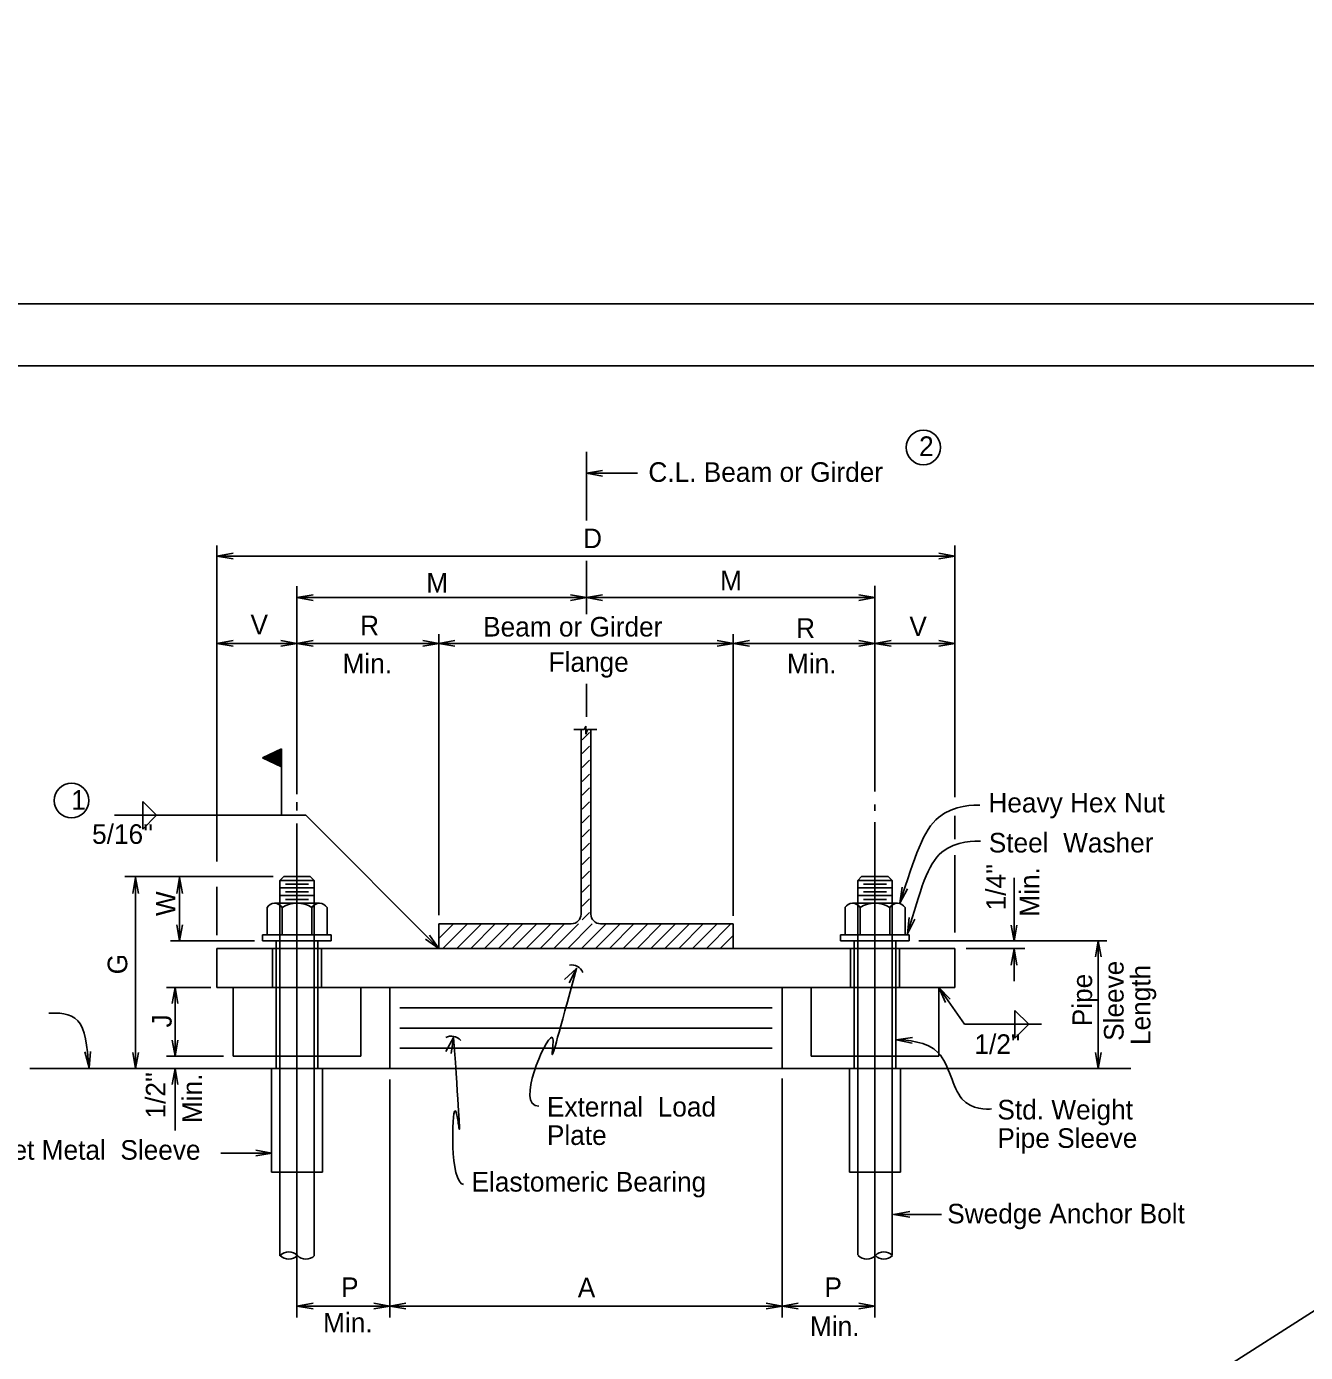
# Model space of a CAD drawing. Extents: x 113 to 232, y -103 to -27.
# Drawn here: x 159.73 to 165.17, y -32.24 to -26.61 of the extents above; entities that cross this region are included whole.
import ezdxf

# ---------------------------------------------------------------- set-up
doc = ezdxf.new("R2010")
doc.units = 0
for name, color, linetype in [('1', 7, 'Continuous'), ('B_Border', 7, 'Continuous'), ('B_Dimension', 7, 'Continuous'), ('B_No_Plot', 7, 'Continuous')]:
    doc.layers.add(name, color=color, linetype=linetype)

msp = doc.modelspace()

# ---------------------------------------------------------------- linework, layer by layer
at = {"layer": '1'}
for p, q in [((147.5029, -43.3409), (173.7742, -26.6088)), ((162.1117, -28.7088), (162.1117, -28.4165)), ((162.1117, -28.5077), (162.329, -28.5077)), ((160.5416, -30.1572), (160.5416, -28.8149)), ((163.6775, -29.8845), (163.6775, -28.8149)), ((160.5416, -28.8595), (163.6775, -28.8595)), ((162.1117, -29.1067), (162.1117, -28.8797)), ((160.8816, -29.8713), (160.8816, -28.9872)), ((163.3375, -29.8606), (163.3375, -28.9863)), ((160.8816, -29.0363), (162.1117, -29.0363)), ((162.1117, -29.0363), (163.3375, -29.0363)), ((161.4845, -30.3862), (161.4845, -29.1915)), ((162.7345, -30.3886), (162.7345, -29.1915)), ((160.5416, -29.231), (160.8816, -29.231)), ((160.8816, -29.231), (161.4845, -29.231)), ((161.4845, -29.231), (162.7359, -29.231)), ((162.7359, -29.231), (163.3375, -29.231)), ((163.3375, -29.231), (163.6775, -29.231)), ((162.1117, -29.5426), (162.1117, -29.4022)), ((162.1014, -29.597), (162.1093, -29.5829)), ((162.1093, -29.5829), (162.1093, -29.616)), ((162.0579, -29.597), (162.1014, -29.597)), ((162.0888, -29.597), (162.0888, -30.3813)), ((162.1093, -29.616), (162.1154, -29.597)), ((162.1154, -29.597), (162.1558, -29.597)), ((162.1303, -30.3813), (162.1303, -29.597)), ((160.816, -29.6793), (160.735, -29.7171)), ((160.816, -29.6793), (160.816, -29.6787)), ((160.816, -29.7548), (160.816, -29.6793)), ((160.735, -29.7171), (160.816, -29.7548)), ((160.816, -29.7548), (160.816, -29.7853)), ((160.816, -29.7853), (160.816, -29.9615)), ((160.2261, -30.0205), (160.2261, -29.9025)), ((160.2261, -29.9025), (160.2851, -29.9615)), ((160.8816, -29.9414), (160.8816, -29.9054)), ((163.3375, -29.9429), (163.3375, -29.9155)), ((160.9189, -29.9615), (160.1068, -29.9615)), ((160.2851, -29.9615), (160.2261, -30.0205)), ((161.4845, -30.5271), (160.9189, -29.9615)), ((163.6775, -30.0629), (163.6775, -29.9632)), ((160.8816, -32.0955), (160.8816, -29.9969)), ((163.3375, -32.0955), (163.3375, -29.99)), ((163.6775, -30.4598), (163.6775, -30.1312)), ((160.781, -30.2217), (160.1497, -30.2217)), ((160.1958, -31.0376), (160.1958, -30.2253)), ((160.3824, -30.495), (160.3824, -30.2253)), ((160.825, -30.2217), (160.8086, -30.238)), ((160.8086, -30.3352), (160.8086, -30.238)), ((160.8086, -30.238), (160.9545, -30.238)), ((160.825, -30.2217), (160.9381, -30.2217)), ((160.833, -30.2543), (160.9301, -30.2543)), ((160.9381, -30.2217), (160.9545, -30.238)), ((160.9545, -30.3352), (160.9545, -30.238)), ((163.2646, -30.238), (163.2809, -30.2217)), ((163.2646, -30.238), (163.4104, -30.238)), ((163.2646, -30.3352), (163.2646, -30.238)), ((163.2646, -30.238), (163.4104, -30.238)), ((163.2809, -30.2217), (163.3941, -30.2217)), ((163.2889, -30.2543), (163.3861, -30.2543)), ((163.3941, -30.2217), (163.4104, -30.238)), ((163.4104, -30.3352), (163.4104, -30.238)), ((163.9288, -30.4962), (163.9288, -30.2272)), ((160.5416, -30.4716), (160.5416, -30.2656)), ((160.8086, -30.2704), (160.9545, -30.2704)), ((160.8086, -30.3028), (160.9545, -30.3028)), ((160.833, -30.2868), (160.9301, -30.2868)), ((160.833, -30.3191), (160.9301, -30.3191)), ((163.2646, -30.2704), (163.4104, -30.2704)), ((163.2646, -30.3028), (163.4104, -30.3028)), ((163.2889, -30.2868), (163.3861, -30.2868)), ((163.2889, -30.3191), (163.3861, -30.3191)), ((160.7542, -30.469), (160.7542, -30.3535)), ((160.7863, -30.3352), (160.9771, -30.3352)), ((160.8086, -31.0376), (160.8086, -30.3352)), ((160.8186, -30.469), (160.8186, -30.3535)), ((160.9447, -30.469), (160.9447, -30.3535)), ((160.9545, -31.0376), (160.9545, -30.3352)), ((161.0093, -30.469), (161.0093, -30.3535)), ((163.2102, -30.469), (163.2102, -30.3535)), ((163.2422, -30.3352), (163.433, -30.3352)), ((163.2646, -31.0376), (163.2646, -30.3352)), ((163.2745, -30.469), (163.2745, -30.3535)), ((163.4007, -30.469), (163.4007, -30.3535)), ((163.4104, -31.0376), (163.4104, -30.3352)), ((163.4652, -30.469), (163.4652, -30.3535)), ((162.0471, -30.4229), (161.4845, -30.4229)), ((161.4845, -30.4229), (161.4845, -30.5271)), ((162.7345, -30.4229), (162.1719, -30.4229)), ((162.7345, -30.5271), (162.7345, -30.4229)), ((160.7357, -30.469), (161.0274, -30.469)), ((160.7357, -30.469), (160.7357, -30.495)), ((161.0274, -30.469), (161.0274, -30.495)), ((163.1917, -30.469), (163.4833, -30.469)), ((163.1917, -30.469), (163.1917, -30.495)), ((163.4833, -30.469), (163.4833, -30.495)), ((160.7005, -30.495), (160.3437, -30.495)), ((160.5416, -30.6938), (160.5416, -30.5271)), ((160.5416, -30.5271), (163.6775, -30.5271)), ((160.7357, -30.495), (161.0274, -30.495)), ((160.7775, -30.6938), (160.7775, -30.5283)), ((160.7931, -30.5283), (160.7931, -30.4953)), ((160.7931, -30.6938), (160.7931, -30.5283)), ((160.9701, -30.5283), (160.9701, -30.4953)), ((160.9701, -30.6936), (160.9701, -30.5283)), ((160.9856, -30.6938), (160.9856, -30.5283)), ((163.1917, -30.495), (163.4833, -30.495)), ((163.2334, -30.6947), (163.2334, -30.5279)), ((163.249, -30.5279), (163.249, -30.4946)), ((163.249, -30.6947), (163.249, -30.5279)), ((163.426, -30.5279), (163.426, -30.4956)), ((163.426, -30.6957), (163.426, -30.5309)), ((163.4416, -30.6957), (163.4416, -30.5309)), ((163.5232, -30.495), (164.3221, -30.495)), ((163.6775, -30.6938), (163.6775, -30.5271)), ((163.7253, -30.5271), (163.9744, -30.5271)), ((163.9288, -30.6671), (163.9288, -30.5295)), ((164.2861, -31.0376), (164.2861, -30.495)), ((160.5151, -30.6938), (160.3275, -30.6938)), ((160.3637, -30.6938), (160.3637, -30.9854)), ((160.5416, -30.6938), (163.6775, -30.6938)), ((160.6108, -30.6938), (160.6108, -30.9854)), ((160.7931, -30.9854), (160.7931, -30.6938)), ((160.9701, -30.9854), (160.9701, -30.6936)), ((161.1524, -30.6938), (161.1524, -30.9854)), ((161.2762, -30.6938), (161.2762, -31.0376)), ((162.9429, -30.6938), (162.9429, -31.0376)), ((163.0667, -30.6938), (163.0667, -30.9854)), ((163.249, -30.9854), (163.249, -30.6947)), ((163.426, -30.9854), (163.426, -30.6957)), ((163.6083, -30.6938), (163.6083, -30.9854)), ((163.6083, -30.6938), (163.7183, -30.8497)), ((161.3179, -30.7798), (162.9012, -30.7798)), ((163.9324, -30.9087), (163.9324, -30.7907)), ((163.9324, -30.7907), (163.9914, -30.8497)), ((161.3179, -30.8658), (162.9012, -30.8658)), ((163.7183, -30.8497), (164.0447, -30.8497)), ((163.9914, -30.8497), (163.9324, -30.9087)), ((160.5691, -30.9854), (160.3275, -30.9854)), ((160.6108, -30.9854), (161.1524, -30.9854)), ((160.7931, -31.0376), (160.7931, -30.9854)), ((160.9701, -31.0376), (160.9701, -30.9854)), ((161.3179, -30.9517), (162.9012, -30.9517)), ((163.0667, -30.9854), (163.6084, -30.9854)), ((163.249, -31.0376), (163.249, -30.9854)), ((163.426, -31.0376), (163.426, -30.9854)), ((159.7458, -31.0376), (164.4241, -31.0376)), ((160.3637, -31.0376), (160.3637, -31.3013)), ((160.7731, -31.4778), (160.7731, -31.0376)), ((160.8086, -31.0376), (160.8086, -31.4778)), ((160.9545, -31.0376), (160.9545, -31.4778)), ((160.9901, -31.4778), (160.9901, -31.0376)), ((163.229, -31.4778), (163.229, -31.0376)), ((163.2646, -31.0376), (163.2646, -31.4778)), ((163.4104, -31.0376), (163.4104, -31.4778)), ((163.446, -31.4778), (163.446, -31.0376)), ((161.2762, -31.0851), (161.2762, -32.0955)), ((162.9429, -31.0806), (162.9429, -32.0955)), ((160.5586, -31.3971), (160.7746, -31.3971)), ((160.9901, -31.4778), (160.7731, -31.4778)), ((160.8086, -31.4778), (160.8086, -31.8344)), ((160.9545, -31.4778), (160.9545, -31.8343)), ((163.446, -31.4778), (163.229, -31.4778)), ((163.2646, -31.4778), (163.2646, -31.8309)), ((163.4104, -31.4778), (163.4104, -31.8311)), ((163.4173, -31.6576), (163.62, -31.6576)), ((160.8816, -32.0478), (161.2762, -32.0478)), ((161.2762, -32.0478), (162.9429, -32.0478)), ((162.9429, -32.0478), (163.3375, -32.0478))]:
    msp.add_line(p, q, dxfattribs=at)
for points in [[(162.0939, -29.6404), (162.1251, -29.6092)], [(160.7704, -29.7335), (160.7704, -29.7007)], [(160.7747, -29.7355), (160.7747, -29.6987)], [(160.779, -29.7375), (160.779, -29.6967)], [(160.7833, -29.7396), (160.7833, -29.6947)], [(160.7876, -29.7416), (160.7876, -29.6926)], [(160.7919, -29.7435), (160.7919, -29.6906)], [(160.7962, -29.7455), (160.7962, -29.6886)], [(160.8005, -29.7475), (160.8005, -29.6866)], [(160.8048, -29.7496), (160.8048, -29.6847)], [(160.8091, -29.7516), (160.8091, -29.6826)], [(160.8134, -29.7535), (160.8134, -29.6806)], [(162.0939, -29.6993), (162.1251, -29.6682)], [(160.736, -29.7175), (160.736, -29.7167)], [(160.7402, -29.7196), (160.7402, -29.7147)], [(160.7446, -29.7216), (160.7446, -29.7127)], [(160.7489, -29.7235), (160.7489, -29.7107)], [(160.7531, -29.7255), (160.7531, -29.7087)], [(160.7575, -29.7275), (160.7575, -29.7067)], [(160.7618, -29.7296), (160.7618, -29.7047)], [(160.7661, -29.7316), (160.7661, -29.7027)], [(162.0939, -29.7583), (162.1251, -29.7271)], [(162.0939, -29.8172), (162.1251, -29.786)], [(162.0939, -29.8761), (162.1251, -29.8449)], [(162.0939, -29.935), (162.1251, -29.9038)], [(162.0939, -29.9939), (162.1251, -29.9628)], [(162.0939, -30.0528), (162.1251, -30.0217)], [(162.0939, -30.1118), (162.1251, -30.0806)], [(162.0939, -30.1707), (162.1251, -30.1395)], [(162.0939, -30.2296), (162.1251, -30.1984)], [(162.0939, -30.2885), (162.1251, -30.2573)], [(162.0939, -30.3474), (162.1251, -30.3163)], [(162.0939, -30.4063), (162.1251, -30.3752)], [(161.4845, -30.4855), (161.5471, -30.4229)], [(161.4845, -30.4266), (161.4882, -30.4229)], [(161.5019, -30.5271), (161.606, -30.4229)], [(161.5608, -30.5271), (161.6649, -30.4229)], [(161.6197, -30.5271), (161.7239, -30.4229)], [(161.6786, -30.5271), (161.7828, -30.4229)], [(161.7375, -30.5271), (161.8417, -30.4229)], [(161.7964, -30.5271), (161.9006, -30.4229)], [(161.8554, -30.5271), (161.9595, -30.4229)], [(161.9143, -30.5271), (162.0185, -30.4229)], [(161.9732, -30.5271), (162.0774, -30.4229)], [(162.0322, -30.5271), (162.1364, -30.4229)], [(162.0911, -30.5271), (162.1953, -30.4229)], [(162.15, -30.5271), (162.2542, -30.4229)], [(162.2089, -30.5271), (162.3131, -30.4229)], [(162.2679, -30.5271), (162.372, -30.4229)], [(162.3268, -30.5271), (162.431, -30.4228)], [(162.3857, -30.5271), (162.4899, -30.4229)], [(162.4447, -30.527), (162.5488, -30.4229)], [(162.5035, -30.5271), (162.6078, -30.4229)], [(162.5625, -30.5271), (162.6667, -30.4229)], [(162.6214, -30.5271), (162.7256, -30.4229)], [(162.6804, -30.5271), (162.7345, -30.4729)], [(160.8923, -30.5271), (160.8923, -30.5271)], [(161.0101, -30.5271), (161.0101, -30.5271)], [(161.0691, -30.5271), (161.0691, -30.5271)], [(163.2309, -30.5271), (163.2309, -30.5271)], [(163.6379, -30.7566), (163.6083, -30.6938), (163.6575, -30.7427)]]:
    msp.add_lwpolyline(points, dxfattribs=at)
for centre in [(163.543, -28.398), (159.9234, -29.8987)]:
    msp.add_circle(centre, 0.0733, dxfattribs=at)
for centre, radius, start, end in [((160.7864, -30.3726), 0.0375, 30.8086, 149.1914), ((160.8817, -30.4532), 0.118, 57.6898, 122.3102), ((160.977, -30.3728), 0.0376, 30.9573, 149.0427), ((163.2423, -30.3726), 0.0375, 30.8086, 149.1914), ((163.3376, -30.4532), 0.118, 57.6898, 122.3102), ((163.433, -30.3728), 0.0376, 30.9573, 149.0427), ((162.0471, -30.3812), 0.0417, 270, 360), ((162.172, -30.3812), 0.0417, 180, 270), ((162.0481, -30.6486), 0.0513, 21.6992, 99.9226), ((161.5381, -30.9515), 0.0513, 40.3962, 118.6196), ((160.8467, -31.8675), 0.0504, 43.7135, 136.2865), ((160.8467, -31.7978), 0.0504, 223.7135, 316.2865), ((160.9196, -31.7978), 0.0504, 223.7135, 316.2865), ((163.3026, -31.7978), 0.0504, 223.7135, 316.2865), ((163.3755, -31.8675), 0.0504, 43.7135, 136.2865), ((163.3755, -31.7978), 0.0504, 223.7135, 316.2865)]:
    msp.add_arc(centre, radius, start, end, dxfattribs=at)
for points in [[(163.7824, -29.9179), (163.7657, -29.9173), (163.5785, -29.9144), (163.5077, -30.1344), (163.4432, -30.3351)], [(163.7856, -30.0718), (163.7692, -30.0712), (163.5919, -30.0646), (163.5308, -30.2737), (163.4764, -30.4653)], [(161.9094, -31.198), (161.8075, -31.198), (162.0698, -30.6123), (161.9094, -31.198), (162.0698, -30.6123)], [(159.8269, -30.8032), (159.8623, -30.8005), (159.9763, -30.8011), (159.9891, -30.9377), (159.9982, -31.0343)], [(161.5891, -31.5301), (161.5309, -31.5267), (161.5473, -30.9055), (161.5891, -31.5301), (161.5473, -30.9055)], [(163.8329, -31.2097), (163.8161, -31.2109), (163.6785, -31.2171), (163.6435, -30.9245), (163.473, -30.9172), (163.4278, -30.9153)]]:
    msp.add_open_spline(points, degree=3, dxfattribs=at)
at = {"layer": 'B_Border'}
msp.add_line((150.5413, -28.0514), (171.618, -28.0514), dxfattribs=at)
at = {"layer": 'B_Dimension'}
for points in [[(162.18, -28.5197), (162.1117, -28.5077), (162.18, -28.4956)], [(160.6099, -28.8716), (160.5416, -28.8595), (160.6099, -28.8475)], [(163.6092, -28.8475), (163.6775, -28.8595), (163.6092, -28.8716)], [(160.9499, -29.0483), (160.8816, -29.0363), (160.9499, -29.0243)], [(162.0434, -29.0243), (162.1117, -29.0363), (162.0434, -29.0483)], [(162.18, -29.0483), (162.1117, -29.0363), (162.18, -29.0243)], [(163.2692, -29.0243), (163.3375, -29.0363), (163.2692, -29.0483)], [(160.6099, -29.243), (160.5416, -29.231), (160.6099, -29.2189)], [(160.8132, -29.2189), (160.8816, -29.231), (160.8132, -29.243)], [(160.9499, -29.243), (160.8816, -29.231), (160.9499, -29.2189)], [(161.4162, -29.2189), (161.4845, -29.231), (161.4162, -29.243)], [(161.5528, -29.243), (161.4845, -29.231), (161.5528, -29.2189)], [(162.6676, -29.2189), (162.7359, -29.231), (162.6676, -29.243)], [(162.8043, -29.243), (162.7359, -29.231), (162.8043, -29.2189)], [(163.2692, -29.2189), (163.3375, -29.231), (163.2692, -29.243)], [(163.4058, -29.243), (163.3375, -29.231), (163.4058, -29.2189)], [(163.6092, -29.2189), (163.6775, -29.231), (163.6092, -29.243)], [(160.1838, -30.2936), (160.1958, -30.2253), (160.2078, -30.2936)], [(160.3703, -30.2936), (160.3824, -30.2253), (160.3944, -30.2936)], [(163.4756, -30.2738), (163.4432, -30.3351), (163.4526, -30.2664)], [(160.3944, -30.4267), (160.3824, -30.495), (160.3703, -30.4267)], [(163.5066, -30.4029), (163.4764, -30.4653), (163.4835, -30.3963)], [(163.9409, -30.4278), (163.9288, -30.4962), (163.9168, -30.4278)], [(161.4447, -30.4703), (161.4845, -30.5271), (161.4277, -30.4873)], [(163.9168, -30.5978), (163.9288, -30.5295), (163.9409, -30.5978)], [(164.2741, -30.5633), (164.2861, -30.495), (164.2981, -30.5633)], [(162.0184, -30.6588), (162.0698, -30.6123), (162.0374, -30.6736)], [(160.3516, -30.7621), (160.3637, -30.6938), (160.3757, -30.7621)], [(160.3757, -30.9171), (160.3637, -30.9854), (160.3516, -30.9171)], [(161.5136, -30.9661), (161.5473, -30.9055), (161.5363, -30.974)], [(163.4956, -30.9302), (163.4278, -30.9153), (163.4966, -30.9061)], [(160.0038, -30.9652), (159.9982, -31.0343), (159.9798, -30.9674)], [(160.2078, -30.9693), (160.1958, -31.0376), (160.1838, -30.9693)], [(164.2981, -30.9693), (164.2861, -31.0376), (164.2741, -30.9693)], [(160.3516, -31.1059), (160.3637, -31.0376), (160.3757, -31.1059)], [(160.7063, -31.3851), (160.7746, -31.3971), (160.7063, -31.4092)], [(163.4856, -31.6696), (163.4173, -31.6576), (163.4856, -31.6456)], [(160.9499, -32.0599), (160.8816, -32.0478), (160.9499, -32.0358)], [(161.2078, -32.0358), (161.2762, -32.0478), (161.2078, -32.0599)], [(161.3445, -32.0599), (161.2762, -32.0478), (161.3445, -32.0358)], [(162.8746, -32.0358), (162.9429, -32.0478), (162.8746, -32.0599)], [(163.0112, -32.0599), (162.9429, -32.0478), (163.0112, -32.0358)], [(163.2692, -32.0358), (163.3375, -32.0478), (163.2692, -32.0599)]]:
    msp.add_lwpolyline(points, dxfattribs=at)
at = {"layer": 'B_No_Plot'}
msp.add_lwpolyline([(149.5897, -27.7878), (171.923, -27.7878), (171.923, -42.0118), (149.5897, -42.0118)], close=True, dxfattribs=at)

# ---------------------------------------------------------------- texts
at = {"layer": '1'}
for s, height, p in [('2', 0.0833, (163.525, -28.4342)), ('C.L. Beam or Girder', 0.083334, (162.3747, -28.5442)), ('D', 0.0833, (162.0972, -28.826)), ('M', 0.0833, (161.4311, -29.0145)), ('M', 0.0833, (162.6796, -29.0053)), ('V', 0.0833, (160.6841, -29.1923)), ('R', 0.0833, (161.1498, -29.1964)), ('Beam or Girder', 0.083334, (161.6725, -29.2016)), ('R', 0.0833, (163.0024, -29.2074)), ('V', 0.0833, (163.4837, -29.1999)), ('Min.', 0.08333, (161.0752, -29.3579)), ('Flange', 0.08333, (161.9505, -29.3515)), ('Min.', 0.08333, (162.9636, -29.3579)), ('1', 0.0833, (159.9223, -29.9377)), ('Heavy Hex Nut', 0.083334, (163.8195, -29.9494)), ("5/16''", 0.08333, (160.0109, -30.0829)), ('Steel  Washer', 0.083334, (163.8211, -30.1195)), ('1/2"', 0.08333, (163.7603, -30.9758)), ('External  Load ', 0.083334, (161.9436, -31.2419)), ('Std. Weight ', 0.083334, (163.8577, -31.2543)), ('Plate', 0.08333, (161.9436, -31.3627)), ('Pipe Sleeve', 0.083334, (163.8577, -31.3751)), ('Sheet Metal  Sleeve', 0.083334, (159.4745, -31.4255)), ('Elastomeric Bearing', 0.083334, (161.6232, -31.5609)), ('Swedge Anchor Bolt', 0.083334, (163.6446, -31.6962)), ('P', 0.0833, (161.0689, -32.0091)), ('A', 0.0833, (162.0747, -32.0103)), ('P', 0.0833, (163.1228, -32.0091)), ('Min.', 0.08333, (160.9924, -32.1596)), ('Min.', 0.08333, (163.0614, -32.1747))]:
    msp.add_text(s, height=height, dxfattribs=at).set_placement(p)
for s, height, p in [("1/4''", 0.08333, (163.8934, -30.3656)), ('Min.', 0.08333, (164.0358, -30.3925)), ('W', 0.0833, (160.3652, -30.3898)), ('G', 0.0833, (160.1604, -30.6374)), ('Sleeve ', 0.08333, (164.394, -30.9203)), ('Pipe', 0.08333, (164.2601, -30.8581)), ('Length', 0.08333, (164.5079, -30.9379)), ('J', 0.0833, (160.3489, -30.8634)), ("1/2''", 0.08333, (160.3226, -31.2502)), ('Min.', 0.08333, (160.4773, -31.2699))]:
    msp.add_text(s, height=height, rotation=90, dxfattribs=at).set_placement(p)

doc.saveas('drawing.dxf')
